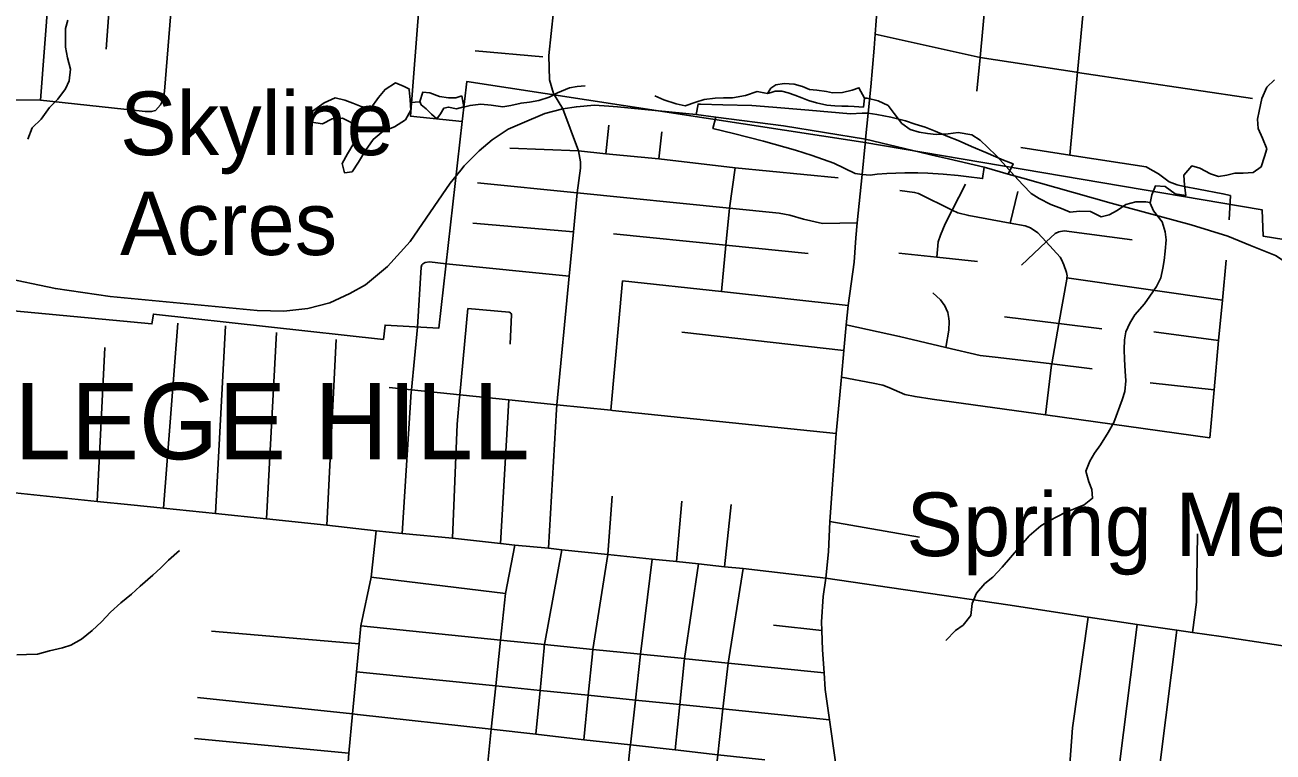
# Model space of a CAD drawing. Extents: x 0 to 34, y 0 to 22.
# Drawn here: x 5.421 to 6.973, y 15.023 to 15.927 of the extents above; entities that cross this region are included whole.
import ezdxf

# ---------------------------------------------------------------- set-up
doc = ezdxf.new("R2010")
doc.units = 0
for name, color, linetype in [('GM_X_City_Street', 7, 'Continuous'), ('GM_X_Corporation', 7, 'Continuous'), ('GM_X_Corporation_Text', 7, 'Continuous'), ('GM_X_Interchange_Ramps', 7, 'Continuous'), ('GM_X_Minor_Lake', 7, 'Continuous'), ('GM_X_Minor_River', 7, 'Continuous'), ('GM_X_State_Route', 7, 'Continuous'), ('GM_X_Township_Subdivision', 7, 'Continuous'), ('GM_X_Unincorporated_Text', 7, 'Continuous'), ('GM_X_US_Route', 7, 'Continuous')]:
    doc.layers.add(name, color=color, linetype=linetype)

msp = doc.modelspace()

# ---------------------------------------------------------------- linework, layer by layer
at = {"layer": 'GM_X_City_Street'}
for points in [[(6.0782, 15.8417), (6.073, 15.8584), (6.0723, 15.8887), (6.0782, 15.9436), (6.0848, 16.0117), (6.0879, 16.0415), (6.0881, 16.0439), (6.0947, 16.1212), (6.1032, 16.2159)], [(6.7292, 15.8641), (6.7295, 15.8678), (6.7378, 15.9562), (6.7561, 16.1506), (6.7562, 16.1518), (6.7563, 16.1521)], [(6.6042, 15.8442), (6.6083, 15.8863), (6.6157, 15.9635)], [(6.4779, 15.9151), (6.6083, 15.8863), (6.7283, 15.868), (6.7295, 15.8678), (6.9469, 15.8351)], [(5.9805, 15.8947), (6.0649, 15.8869)], [(6.7198, 15.7648), (6.7291, 15.864), (6.7292, 15.8641)], [(6.0823, 15.4541), (6.0823, 15.4546), (6.0976, 15.6143), (6.1029, 15.6697), (6.1076, 15.718), (6.1118, 15.7486), (6.1118, 15.7565), (6.1092, 15.7703), (6.0898, 15.8223), (6.0782, 15.8417)], [(6.1433, 15.7667), (6.147, 15.8022)], [(6.2091, 15.7601), (6.2127, 15.794)], [(6.0239, 15.7737), (6.1092, 15.7703), (6.1433, 15.7667), (6.2091, 15.7601), (6.3038, 15.7493), (6.432, 15.7365)], [(6.659, 15.7742), (6.7198, 15.7648), (6.8147, 15.7502), (6.8169, 15.749)], [(6.2868, 15.5953), (6.2923, 15.6531), (6.2967, 15.6989), (6.3038, 15.7493)], [(6.8169, 15.749), (6.8301, 15.7417), (6.8435, 15.7319), (6.8534, 15.7281), (6.8622, 15.7258), (6.88, 15.7225), (6.9102, 15.7169), (6.9197, 15.7146)], [(5.9837, 15.7305), (6.1076, 15.718), (6.2967, 15.6989), (6.3588, 15.6926), (6.3717, 15.6904), (6.3887, 15.6855), (6.4125, 15.68), (6.4555, 15.6809)], [(6.5085, 15.7208), (6.527, 15.7186), (6.5319, 15.7173), (6.5737, 15.6965), (6.5808, 15.693), (6.5944, 15.6897), (6.646, 15.6804), (6.6645, 15.6771), (6.6709, 15.6747), (6.6802, 15.6684), (6.6907, 15.6571), (6.7081, 15.6382), (6.7096, 15.6353), (6.7124, 15.6286), (6.716, 15.619), (6.7165, 15.615), (6.7163, 15.6122), (6.7162, 15.6106), (6.7064, 15.5556), (6.6974, 15.5054), (6.6972, 15.5043), (6.6897, 15.442)], [(6.5548, 15.6379), (6.5561, 15.6571), (6.5593, 15.6654), (6.5649, 15.6793), (6.5737, 15.6965), (6.5903, 15.7289)], [(6.646, 15.6804), (6.6555, 15.7199)], [(6.918, 15.6844), (6.9197, 15.7146)], [(5.9777, 15.6805), (6.1029, 15.6697)], [(6.1526, 15.6672), (6.2923, 15.6531), (6.3946, 15.6428)], [(6.66, 15.6282), (6.6907, 15.6571), (6.7019, 15.6676), (6.7065, 15.6697), (6.713, 15.6707), (6.7975, 15.6598)], [(6.5075, 15.643), (6.5548, 15.6379), (6.605, 15.6325)], [(5.9444, 15.6299), (6.0976, 15.6143)], [(6.436, 15.4891), (6.4755, 15.4814), (6.4876, 15.4789), (6.4951, 15.476), (6.5147, 15.4673), (6.5276, 15.4647), (6.5488, 15.4616), (6.6897, 15.442), (6.894, 15.4137), (6.8995, 15.4733), (6.905, 15.5343), (6.9097, 15.5848), (6.9142, 15.6343)], [(6.7163, 15.6122), (6.9097, 15.5848)], [(6.1494, 15.4477), (6.1639, 15.6088)], [(6.1639, 15.6088), (6.2868, 15.5953), (6.4444, 15.5782)], [(6.566, 15.5259), (6.5697, 15.5474), (6.5699, 15.558), (6.5695, 15.562), (6.5682, 15.5691), (6.5663, 15.5739), (6.5646, 15.5775), (6.5591, 15.5852), (6.5498, 15.5938)], [(5.9615, 15.4662), (5.9616, 15.467), (5.9716, 15.5742)], [(5.9716, 15.5742), (6.0228, 15.5697), (6.0236, 15.5694), (6.0244, 15.569), (6.0254, 15.568), (6.0257, 15.567), (6.0242, 15.5301)], [(6.6388, 15.5641), (6.7064, 15.5556), (6.7597, 15.5489)], [(5.5931, 15.326), (5.6109, 15.5559)], [(5.6577, 15.3193), (5.6701, 15.5527)], [(5.9013, 15.4722), (5.9014, 15.4732), (5.9091, 15.5509)], [(6.4421, 15.5541), (6.5083, 15.5396), (6.566, 15.5259), (6.6085, 15.5157), (6.6309, 15.5133), (6.6974, 15.5054), (6.7476, 15.4994)], [(5.7212, 15.3127), (5.7338, 15.5445)], [(5.7962, 15.3048), (5.8077, 15.5357)], [(6.2378, 15.5448), (6.4391, 15.5219)], [(6.8243, 15.5452), (6.905, 15.5343)], [(5.5108, 15.3345), (5.5201, 15.526)], [(5.8737, 15.4761), (5.9014, 15.4732), (5.9616, 15.467), (6.0227, 15.4607), (6.0823, 15.4546), (6.1494, 15.4477), (6.1516, 15.4475)], [(5.8897, 15.2946), (5.9011, 15.4706), (5.9013, 15.4722)], [(6.8199, 15.4818), (6.8995, 15.4733)], [(5.9524, 15.289), (5.9582, 15.4305), (5.9613, 15.4637), (5.9615, 15.4662)], [(6.012, 15.2821), (6.0227, 15.4607)], [(6.072, 15.2762), (6.0817, 15.4486), (6.0823, 15.4541)], [(6.1516, 15.4475), (6.1516, 15.4475), (6.4295, 15.4189)], [(5.4006, 15.3461), (5.5108, 15.3345), (5.5525, 15.3303), (5.5931, 15.326), (5.6577, 15.3193), (5.7212, 15.3127), (5.7962, 15.3048), (5.8577, 15.298), (5.8897, 15.2946), (5.9524, 15.289), (6.012, 15.2821), (6.03, 15.2801), (6.072, 15.2762), (6.0883, 15.2744), (6.1454, 15.2685), (6.2008, 15.2629), (6.2309, 15.2599), (6.2583, 15.2568), (6.2907, 15.2533), (6.3139, 15.2509), (6.4165, 15.2392), (6.6429, 15.2058), (6.7426, 15.1905), (6.8038, 15.1813), (6.853, 15.1746), (6.8725, 15.1716), (6.9082, 15.1664), (7.0179, 15.1499)], [(6.1265, 15.146), (6.1269, 15.1506), (6.1454, 15.2685), (6.1508, 15.3411)], [(6.2309, 15.2599), (6.2378, 15.3349)], [(6.2907, 15.2533), (6.2991, 15.3306)], [(6.4217, 15.3094), (6.5329, 15.2901)], [(5.7994, 14.7287), (5.8036, 14.7837), (5.8078, 14.8371), (5.8123, 14.8957), (5.8135, 14.9116), (5.8172, 14.9514), (5.8227, 15.0103), (5.8238, 15.0217), (5.8283, 15.0704), (5.8331, 15.1226), (5.8363, 15.1573), (5.8384, 15.1798), (5.8514, 15.2403), (5.8577, 15.298)], [(6.8725, 15.1716), (6.8776, 15.2094), (6.8785, 15.2943)], [(5.9646, 14.6836), (5.9672, 14.7104), (5.9726, 14.7656), (5.9779, 14.8204), (5.9835, 14.8784), (5.989, 14.9347), (5.9946, 14.9926), (5.9947, 14.9935), (6.0007, 15.0512), (6.0063, 15.1051), (6.0122, 15.1622), (6.0182, 15.2201), (6.03, 15.2801)], [(6.0666, 15.1554), (6.0668, 15.1567), (6.0883, 15.2744)], [(6.1663, 14.6603), (6.1668, 14.6642), (6.1712, 14.7045), (6.1712, 14.7102), (6.17, 14.7149), (6.1679, 14.7194), (6.1454, 14.7435), (6.144, 14.7461), (6.1438, 14.7474), (6.1436, 14.7485), (6.1444, 14.7549), (6.1495, 14.8036), (6.1556, 14.8611), (6.1616, 14.918), (6.1675, 14.9747), (6.1734, 15.0304), (6.1736, 15.0319), (6.1798, 15.0876), (6.1861, 15.1446), (6.2008, 15.2629)], [(6.2295, 15.0256), (6.2352, 15.082), (6.2411, 15.1391), (6.2583, 15.2568)], [(5.8514, 15.2403), (6.0182, 15.2201)], [(6.2769, 14.9701), (6.2824, 15.0197), (6.2887, 15.0766), (6.2951, 15.1336), (6.3139, 15.2509)], [(5.8384, 15.1798), (6.0122, 15.1622), (6.0668, 15.1567), (6.1269, 15.1506), (6.1821, 15.145), (6.1821, 15.145)], [(6.3515, 15.1805), (6.4116, 15.174)], [(6.7127, 14.9065), (6.7231, 15.053), (6.7426, 15.1905)], [(6.7735, 14.9063), (6.7826, 15.0145), (6.8038, 15.1813)], [(5.6527, 15.1731), (5.8363, 15.1573)], [(6.8236, 14.9014), (6.8322, 15.0099), (6.853, 15.1746)], [(6.0562, 15.045), (6.0614, 15.0995), (6.0664, 15.1526), (6.0666, 15.1554)], [(6.1159, 15.0383), (6.1213, 15.0935), (6.1264, 15.1451), (6.1265, 15.146)], [(6.1821, 15.145), (6.1861, 15.1446), (6.2411, 15.1391), (6.2427, 15.1389), (6.2427, 15.1389)], [(6.2427, 15.1389), (6.2951, 15.1336), (6.4145, 15.1215)], [(5.8331, 15.1226), (6.0063, 15.1051), (6.0614, 15.0995), (6.1213, 15.0935), (6.1798, 15.0876), (6.2352, 15.082), (6.2887, 15.0766), (6.4213, 15.0632)], [(5.6354, 15.0907), (5.8283, 15.0704), (5.8341, 15.0698)], [(5.8341, 15.0698), (5.8342, 15.0698), (6.0007, 15.0512), (6.0562, 15.045), (6.1159, 15.0383), (6.1736, 15.0319), (6.2295, 15.0256), (6.2824, 15.0197), (6.3407, 15.0132)], [(5.6316, 15.0398), (5.8238, 15.0217)]]:
    msp.add_lwpolyline(points, dxfattribs=at)
at = {"layer": 'GM_X_Corporation'}
for points in [[(7.1222, 15.6381), (6.9605, 15.6641), (6.9592, 15.6968), (6.4625, 15.7812), (5.9702, 15.8563), (5.9645, 15.8066), (5.9003, 15.8132), (5.9183, 16.0488)], [(5.3269, 14.8644), (5.36, 15.3466), (5.3844, 15.5735), (5.5787, 15.5551), (5.5807, 15.5674), (5.8665, 15.5358), (5.8686, 15.5537), (5.9354, 15.5498), (5.9645, 15.8066), (5.9702, 15.8563), (6.4625, 15.7812), (6.9592, 15.6968), (6.9605, 15.6641), (7.1222, 15.6381)]]:
    msp.add_lwpolyline(points, dxfattribs=at)
at = {"layer": 'GM_X_Interchange_Ramps'}
for points in [[(6.4694, 15.8172), (6.4619, 15.817), (6.4474, 15.8164), (6.3954, 15.8208), (6.3507, 15.8246), (6.3246, 15.8264), (6.2887, 15.8275), (6.261, 15.8282), (6.2579, 15.8284), (6.2556, 15.8154)], [(6.2798, 15.8121), (6.2763, 15.7978), (6.3019, 15.7916), (6.3392, 15.7822), (6.3789, 15.7709), (6.3996, 15.7643), (6.4265, 15.755), (6.4531, 15.7419), (6.4616, 15.741)], [(6.6435, 15.7414), (6.6494, 15.7541), (6.6373, 15.7588), (6.6154, 15.7682), (6.5976, 15.7757), (6.5811, 15.7831), (6.5681, 15.7882), (6.5527, 15.7947), (6.54, 15.7996), (6.5277, 15.8034), (6.5157, 15.8074), (6.4974, 15.8119), (6.48, 15.8155), (6.4694, 15.8172)], [(6.4616, 15.741), (6.4717, 15.74), (6.4805, 15.7414), (6.4924, 15.742), (6.5036, 15.7426), (6.5149, 15.7428), (6.531, 15.7431), (6.5436, 15.7426), (6.5627, 15.7412), (6.5811, 15.7395), (6.5911, 15.7383), (6.6115, 15.7357), (6.6133, 15.7501)]]:
    msp.add_lwpolyline(points, dxfattribs=at)
at = {"layer": 'GM_X_Minor_Lake'}
for points in [[(5.8922, 15.8501), (5.8815, 15.8546), (5.8687, 15.8466), (5.8605, 15.8365), (5.8508, 15.8234), (5.839, 15.8252), (5.8285, 15.8296), (5.8187, 15.8332), (5.8066, 15.8362), (5.7928, 15.83), (5.7785, 15.8197), (5.7771, 15.8057), (5.7907, 15.8039), (5.803, 15.81), (5.8159, 15.8109), (5.8283, 15.8045), (5.8338, 15.793), (5.8297, 15.7798), (5.8218, 15.7667), (5.8154, 15.7543), (5.8182, 15.7429), (5.8277, 15.7442), (5.8356, 15.7561), (5.8443, 15.7708), (5.8537, 15.7842), (5.8664, 15.7946), (5.8802, 15.8), (5.8941, 15.8088), (5.9005, 15.8208), (5.9, 15.8337), (5.8987, 15.8459), (5.8989, 15.8468)], [(5.8989, 15.8468), (5.8922, 15.8501)], [(5.9639, 15.8385), (5.9616, 15.8377), (5.9566, 15.8363), (5.9475, 15.8361), (5.9365, 15.8379), (5.9245, 15.8423), (5.9158, 15.8433), (5.9117, 15.8316), (5.9135, 15.8273), (5.9199, 15.8223), (5.9262, 15.8157), (5.9329, 15.8102), (5.9376, 15.8162), (5.9419, 15.8233), (5.9476, 15.8247), (5.9575, 15.8226), (5.9665, 15.8248)], [(6.4648, 15.8357), (6.4578, 15.8487), (6.4494, 15.8458), (6.4372, 15.8427), (6.425, 15.8422), (6.4175, 15.8439), (6.4054, 15.8457), (6.3963, 15.8463), (6.3876, 15.8503), (6.3774, 15.8531), (6.3649, 15.8538), (6.3546, 15.8521), (6.3481, 15.8481), (6.3441, 15.8417), (6.3487, 15.8428), (6.3537, 15.8442), (6.362, 15.8444), (6.37, 15.8423), (6.3779, 15.8395), (6.3869, 15.8362), (6.3952, 15.8326), (6.405, 15.8297), (6.4179, 15.8268), (6.4277, 15.8262), (6.4364, 15.8256), (6.4444, 15.8258), (6.452, 15.8253), (6.4634, 15.8246)], [(5.9665, 15.8248), (5.9639, 15.8385)], [(6.4634, 15.8246), (6.4648, 15.8357)]]:
    msp.add_lwpolyline(points, dxfattribs=at)
at = {"layer": 'GM_X_Minor_River'}
for points in [[(5.4741, 15.9327), (5.4712, 15.9221), (5.4713, 15.9115), (5.4714, 15.8989), (5.4737, 15.8859), (5.4776, 15.8718), (5.4757, 15.8574), (5.4713, 15.8472), (5.4618, 15.8345), (5.4513, 15.8241), (5.4411, 15.8095), (5.4298, 15.7988), (5.4245, 15.7848)], [(6.9744, 15.8585), (6.9647, 15.8492), (6.9587, 15.8353), (6.9552, 15.8194), (6.9531, 15.8096), (6.9543, 15.7981), (6.9594, 15.7858), (6.9647, 15.7728), (6.9622, 15.763), (6.9577, 15.7505), (6.9481, 15.7435), (6.9355, 15.7423), (6.9253, 15.7426), (6.9153, 15.7401), (6.905, 15.7385), (6.8948, 15.7418), (6.8817, 15.7486), (6.8715, 15.7515), (6.8617, 15.7399), (6.8626, 15.7277), (6.8642, 15.7148), (6.8509, 15.717), (6.8386, 15.726), (6.8264, 15.7267), (6.822, 15.7154), (6.8198, 15.7052), (6.8238, 15.6956), (6.8349, 15.682), (6.8387, 15.6697), (6.8396, 15.6595), (6.8385, 15.6454), (6.8371, 15.634)], [(6.1173, 15.8509), (6.1075, 15.8504), (6.0979, 15.8487), (6.0829, 15.8422), (6.0725, 15.8368), (6.0599, 15.8329), (6.0481, 15.8309), (6.0378, 15.8296), (6.0248, 15.8265), (6.0149, 15.8249), (6.0005, 15.8271), (5.9876, 15.8282), (5.9743, 15.8266), (5.9663, 15.8247)], [(6.3441, 15.8417), (6.3396, 15.8425), (6.3313, 15.8438), (6.3166, 15.8392), (6.3005, 15.8362), (6.2895, 15.836), (6.2792, 15.8355), (6.2655, 15.834), (6.2552, 15.8308), (6.2418, 15.8262), (6.2304, 15.8287), (6.2153, 15.8337), (6.2041, 15.8385)], [(5.9119, 15.8312), (5.9001, 15.8303)], [(6.82, 15.7059), (6.8142, 15.7069), (6.802, 15.7068), (6.7898, 15.7036), (6.779, 15.6959), (6.769, 15.6908), (6.759, 15.6884), (6.7455, 15.6948), (6.7318, 15.6952), (6.7204, 15.6939), (6.7095, 15.6984), (6.6963, 15.7036), (6.6817, 15.7112), (6.6719, 15.7172), (6.6619, 15.7277), (6.6508, 15.7394), (6.6408, 15.7506), (6.6282, 15.7646), (6.6182, 15.7744), (6.6086, 15.7834), (6.5981, 15.7901), (6.5811, 15.7932), (6.5689, 15.7912), (6.5536, 15.7904), (6.543, 15.7918), (6.5328, 15.7936), (6.5215, 15.7969), (6.511, 15.8044), (6.5015, 15.8168), (6.4941, 15.8265), (6.4817, 15.8325), (6.4681, 15.8355), (6.4648, 15.8357)], [(6.8371, 15.634), (6.8357, 15.6242), (6.8332, 15.6125), (6.8276, 15.6016), (6.8193, 15.5896), (6.8126, 15.5799), (6.8009, 15.5665), (6.7945, 15.556), (6.7894, 15.5454), (6.788, 15.5352), (6.7877, 15.5234), (6.7881, 15.5109), (6.7889, 15.4964), (6.7894, 15.4842), (6.7883, 15.4713), (6.785, 15.4607), (6.7748, 15.4325), (6.7677, 15.4201), (6.7582, 15.4047), (6.7507, 15.3943), (6.7448, 15.3845), (6.7399, 15.3721), (6.7438, 15.3587), (6.7473, 15.3491), (6.7482, 15.3384), (6.7378, 15.3303), (6.7266, 15.3256), (6.7143, 15.3206), (6.7047, 15.3159), (6.6951, 15.3108), (6.6839, 15.3042), (6.6696, 15.2916), (6.659, 15.2797), (6.6461, 15.2648), (6.6359, 15.2529), (6.6242, 15.2403), (6.6145, 15.2325), (6.604, 15.2206), (6.5987, 15.2078), (6.5968, 15.1926), (6.5874, 15.1807), (6.5778, 15.1741), (6.5657, 15.1615)], [(5.4108, 15.1439), (5.423, 15.144), (5.4367, 15.1445), (5.4516, 15.1487), (5.4677, 15.1524), (5.478, 15.156), (5.4911, 15.1633), (5.5043, 15.174), (5.5159, 15.1847), (5.5273, 15.197), (5.5401, 15.2085), (5.5533, 15.2192), (5.5641, 15.2292), (5.5801, 15.2429), (5.5898, 15.2518), (5.5995, 15.2614), (5.6131, 15.2733)]]:
    msp.add_lwpolyline(points, dxfattribs=at)
at = {"layer": 'GM_X_State_Route'}
for points in [[(5.9627, 15.7461), (5.9671, 15.7516), (5.9855, 15.7703), (6.002, 15.7838), (6.0217, 15.7973), (6.039, 15.8048), (6.0674, 15.8167), (6.0898, 15.8223), (6.1065, 15.8251), (6.1289, 15.827), (6.1468, 15.8257)], [(6.1468, 15.8257), (6.1578, 15.8249), (6.2556, 15.8154), (6.2798, 15.8121), (6.364, 15.8012), (6.466, 15.7849)], [(4.6332, 15.782), (4.7176, 15.7753), (4.959, 15.7532), (4.9968, 15.7493), (5.0379, 15.742), (5.0859, 15.7305), (5.1254, 15.7187), (5.201, 15.6901), (5.3286, 15.6339), (5.3828, 15.616), (5.3914, 15.6131), (5.4588, 15.599), (5.5268, 15.5892), (5.7096, 15.5717), (5.7429, 15.5711), (5.7725, 15.5744), (5.8001, 15.5813), (5.8247, 15.5928), (5.8445, 15.6036), (5.8718, 15.6263), (5.8997, 15.6575), (5.9497, 15.7302), (5.9627, 15.7461)], [(6.466, 15.7849), (6.5543, 15.7638)], [(6.5543, 15.7638), (6.5692, 15.7602), (6.6133, 15.7501), (6.6435, 15.7414), (6.6616, 15.7363), (6.7026, 15.7247), (6.7712, 15.7051), (6.871, 15.6782), (6.9165, 15.6643), (6.9444, 15.6525), (6.9756, 15.6403), (7.0026, 15.6225), (7.0332, 15.6017), (7.062, 15.578), (7.2557, 15.428), (7.3428, 15.3613), (7.3665, 15.3432), (7.375, 15.3384)]]:
    msp.add_lwpolyline(points, dxfattribs=at)
at = {"layer": 'GM_X_Township_Subdivision'}
for points in [[(5.5845, 16.3492), (5.5825, 16.3306), (5.5813, 16.3253), (5.5789, 16.3198), (5.5641, 16.3), (5.5609, 16.2934), (5.5585, 16.2827), (5.5577, 16.2722), (5.5503, 16.1649), (5.5478, 16.1247), (5.5451, 16.1168), (5.5399, 16.1092), (5.4864, 16.0372), (5.4518, 15.9911), (5.4511, 15.9791), (5.4502, 15.9637), (5.4401, 15.8331)], [(5.5577, 16.2722), (5.6156, 16.2678), (5.6217, 16.2658), (5.6252, 16.2617), (5.6075, 16.0089), (5.5945, 15.8445), (5.5933, 15.8347), (5.5895, 15.8274), (5.5833, 15.8204), (5.5783, 15.8191), (5.5702, 15.819), (5.5594, 15.8204), (5.4401, 15.8331), (5.4019, 15.8337)], [(5.5221, 15.8965), (5.5254, 15.9416), (5.5264, 15.9549), (5.5305, 15.9634), (5.5498, 15.9907), (5.5575, 15.9997), (5.5662, 16.0087), (5.5734, 16.011), (5.586, 16.0105), (5.6075, 16.0089)], [(5.9091, 15.5509), (5.9136, 15.6256), (5.9144, 15.6287), (5.9156, 15.6298)], [(5.9156, 15.6298), (5.9186, 15.6313), (5.924, 15.6324), (5.9444, 15.6299)]]:
    msp.add_lwpolyline(points, dxfattribs=at)
at = {"layer": 'GM_X_US_Route'}
for points in [[(6.4766, 15.898), (6.4779, 15.9151), (6.4804, 15.9485)], [(6.4654, 15.7791), (6.466, 15.7849), (6.4694, 15.8172), (6.4727, 15.8496), (6.4766, 15.898)], [(6.454, 15.6623), (6.4555, 15.6809), (6.4616, 15.741), (6.4654, 15.7791)], [(6.4285, 15.0103), (6.4213, 15.0632), (6.416, 15.1009), (6.4145, 15.1215), (6.4124, 15.1501), (6.4116, 15.174), (6.4112, 15.1847), (6.4135, 15.2162), (6.4165, 15.2392), (6.4198, 15.2719), (6.4217, 15.3094), (6.4295, 15.4189), (6.436, 15.4891), (6.4391, 15.5219), (6.4421, 15.5541), (6.4444, 15.5782), (6.4517, 15.6318), (6.454, 15.6623)]]:
    msp.add_lwpolyline(points, dxfattribs=at)

# ---------------------------------------------------------------- texts
at = {"layer": 'GM_X_Corporation_Text'}
msp.add_text('NORTH COLLEGE HILL', height=0.094697, rotation=0, dxfattribs=at).set_placement((4.662, 15.3869))
at = {"layer": 'GM_X_Unincorporated_Text'}
for s, height, p in [('Skyline', 0.07898, (5.5392, 15.7649)), ('Acres', 0.07898, (5.5392, 15.6407)), ('Spring Meadows', 0.078977, (6.5167, 15.2665))]:
    msp.add_text(s, height=height, rotation=0, dxfattribs=at).set_placement(p)

doc.saveas('drawing.dxf')
